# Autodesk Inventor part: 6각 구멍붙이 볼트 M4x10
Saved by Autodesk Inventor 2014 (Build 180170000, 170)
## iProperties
Created: 2026-07
Part Number: 6각 구멍붙이 볼트 M4x10
Material: 일반
Document SubType Name: Modeling
Designer: dg
Density: 1 g/cm^3
Appearance: 기본값
Author: dg
Author: jhkim
Description: 6각머리 태핑 나사
Creation Date: 2026-07-02
Sending System: Autodesk Inventor 2027
Preprocessor: ST-DEVELOPER v20.1
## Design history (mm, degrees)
node "6각 구멍붙이 볼트 M4x101"
body "Solid1"
node "기준1"
